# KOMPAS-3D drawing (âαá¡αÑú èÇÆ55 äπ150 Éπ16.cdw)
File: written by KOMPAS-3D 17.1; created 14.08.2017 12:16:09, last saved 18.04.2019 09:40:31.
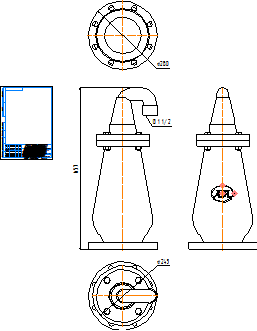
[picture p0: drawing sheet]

Sheet 1: A4, portrait

Title block, sheet 1: name: Гранрег КАТ55 Ду150 Ру16; material: Внимание! Данный продукт является объектом авторского права ООО «Торговый Дом АДЛ». / Запрещается изменение, копирование, распространение / (в том числе путем копирования на другие сайты и ресурсы в Интернете) / или любое иное использование информации и объектов без предварительного / согласия правообладателя (ООО «Торговый Дом АДЛ»).; mass: 116,3; sheets: 1; organisation: ООО "Торговый дом АДЛ"; sheet format: A4; stored path: \\adlc.lan\data\АДЛ_ПКД\3D-модели\ADL production\Клапаны КАТ ГРАНРЕГ\КАТ55\KOMPAS 2D\Гранрег КАТ55 Ду150 Ру16.cdw

Views: Вид 1, Проекционный вид 2, Проекционный вид 3, Проекционный вид 4
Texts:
  kka
  adl
Dimensions and other numbers on the sheet: 657; 280; 245; 1:1; 1; 116,3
